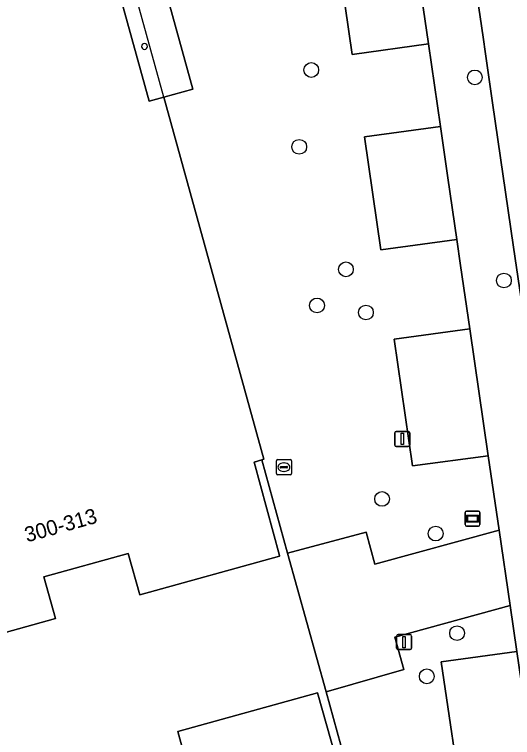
# Model space of a CAD drawing. Extents: x 159053 to 160042, y 380449 to 381423.
# Drawn here: x 159271.09 to 159304.08, y 381110.68 to 381158.52 of the extents above; entities that cross this region are included whole.
import ezdxf

# ---------------------------------------------------------------- set-up
doc = ezdxf.new("R2010")
doc.units = 0
for name, color, linetype in [('IMGEO_Boom', 7, 'Continuous'), ('IMGEO_Erf', 7, 'Continuous'), ('IMGEO_Groenvoorziening', 7, 'Continuous'), ('IMGEO_Informatiebord', 7, 'Continuous'), ('IMGEO_Lichtmast', 7, 'Continuous'), ('IMGEO_Pand', 7, 'Continuous'), ('IMGEO_Pand_nummerreeks', 7, 'Continuous'), ('IMGEO_Pand_overbouw', 7, 'Continuous'), ('IMGEO_Parkeervlak_open', 7, 'Continuous'), ('IMGEO_Rijbaan_lokaal_open', 7, 'Continuous'), ('IMGEO_Rioolput', 7, 'Continuous'), ('IMGEO_Verkeersbordpaal', 7, 'Continuous'), ('IMGEO_Voetpad_open', 7, 'Continuous')]:
    doc.layers.add(name, color=color, linetype=linetype)

msp = doc.modelspace()

# ---------------------------------------------------------------- linework, layer by layer
at = {"layer": 'IMGEO_Boom'}
for centre in [(159290.748, 381154.842), (159301.582, 381154.349), (159289.951, 381149.757), (159293.046, 381141.653), (159303.506, 381140.914), (159291.131, 381139.263), (159294.371, 381138.796), (159295.438, 381126.463), (159298.991, 381124.172), (159300.405, 381117.58), (159298.401, 381114.722)]:
    msp.add_circle(centre, 0.489, dxfattribs=at)
at = {"layer": 'IMGEO_Erf'}
msp.add_lwpolyline([(159267.012, 381106.896), (159276.276, 381109.489), (159277.044, 381106.744), (159282.667, 381108.318), (159281.903, 381111.077), (159291.153, 381113.639), (159292.923, 381107.382), (159293.441, 381107.525), (159291.727, 381113.703), (159289.185, 381122.866), (159287.469, 381129.052), (159286.976, 381128.898), (159288.643, 381122.722), (159288.656, 381122.674), (159279.389, 381120.108), (159278.627, 381122.858), (159273.045, 381121.304), (159273.81, 381118.558), (159264.542, 381115.978)], dxfattribs=at)
at = {"layer": 'IMGEO_Groenvoorziening'}
for points in [[(159269.491, 381169.977), (159277.74, 381172.284), (159278.791, 381168.465), (159282.912, 381153.581), (159280.978, 381153.047), (159287.62, 381129.099), (159287.469, 381129.052), (159289.185, 381122.866), (159294.391, 381124.259), (159294.952, 381122.145), (159303.192, 381124.392), (159302.473, 381129.318), (159297.464, 381128.646), (159296.246, 381137.035), (159301.249, 381137.708), (159300.637, 381141.908), (159300.386, 381143.634), (159295.361, 381142.946), (159294.267, 381150.411), (159299.3, 381151.1), (159298.503, 381156.571), (159293.468, 381155.863), (159292.017, 381165.794)], [(159301.734, 381099.495), (159306.727, 381100.183), (159305.82, 381106.393), (159300.832, 381105.715), (159299.362, 381115.674), (159304.363, 381116.374), (159303.921, 381119.402), (159296.289, 381117.311), (159296.87, 381115.183), (159291.727, 381113.703), (159293.441, 381107.525), (159293.597, 381107.568), (159302.903, 381073.889), (159297.014, 381072.255), (159297.723, 381069.615), (159285.651, 381066.276), (159287.134, 381060.86), (159289.094, 381061.4), (159287.696, 381066.465), (159297.411, 381069.143), (159298.793, 381064.19), (159309.233, 381066.896)]]:
    msp.add_lwpolyline(points, dxfattribs=at)
at = {"layer": 'IMGEO_Informatiebord'}
for p, q in [((159300.931, 381124.763), (159300.931, 381125.563)), ((159300.931, 381125.563), (159300.931, 381124.763)), ((159301.031, 381125.663), (159301.821, 381125.663)), ((159301.821, 381125.663), (159301.031, 381125.663)), ((159301.921, 381125.563), (159301.921, 381124.763)), ((159301.921, 381124.763), (159301.921, 381125.563)), ((159301.821, 381124.663), (159301.031, 381124.663)), ((159301.031, 381124.663), (159301.821, 381124.663))]:
    msp.add_line(p, q, dxfattribs=at)
for points in [[(159301.032, 381125.395), (159301.82, 381125.395), (159301.82, 381124.931), (159301.032, 381124.931), (159301.032, 381125.395)], [(159301.097, 381125.33), (159301.097, 381124.996), (159301.755, 381124.996), (159301.755, 381125.33), (159301.097, 381125.33)]]:
    msp.add_lwpolyline(points, dxfattribs=at)
for centre, start, end in [((159301.031, 381125.563), 90, 180), ((159301.031, 381125.563), 90, 180), ((159301.821, 381125.563), 0, 90), ((159301.821, 381125.563), 360, 90), ((159301.031, 381124.763), 180, 270), ((159301.031, 381124.763), 180, 270), ((159301.821, 381124.763), 270, 0), ((159301.821, 381124.763), 270, 0)]:
    msp.add_arc(centre, 0.1, start, end, dxfattribs=at)
at = {"layer": 'IMGEO_Lichtmast'}
for p, q in [((159296.403, 381116.593), (159296.403, 381117.393)), ((159296.403, 381117.393), (159296.403, 381116.593)), ((159296.503, 381117.493), (159297.293, 381117.493)), ((159297.293, 381117.493), (159296.503, 381117.493)), ((159297.393, 381117.393), (159297.393, 381116.593)), ((159297.393, 381116.593), (159297.393, 381117.393)), ((159297.293, 381116.493), (159296.503, 381116.493)), ((159296.503, 381116.493), (159297.293, 381116.493))]:
    msp.add_line(p, q, dxfattribs=at)
msp.add_lwpolyline([(159296.823, 381117.368), (159296.973, 381117.368), (159296.973, 381116.618), (159296.823, 381116.618), (159296.823, 381117.368)], dxfattribs=at)
for centre, start, end in [((159296.503, 381117.393), 90, 180), ((159296.503, 381117.393), 90, 180), ((159297.293, 381117.393), 0, 90), ((159297.293, 381117.393), 360, 90), ((159296.503, 381116.593), 180, 270), ((159296.503, 381116.593), 180, 270), ((159297.293, 381116.593), 270, 0), ((159297.293, 381116.593), 270, 0)]:
    msp.add_arc(centre, 0.1, start, end, dxfattribs=at)
at = {"layer": 'IMGEO_Pand'}
msp.add_lwpolyline([(159253.135, 381159.05), (159253.4, 381158.117), (159253.22, 381158.059), (159254.513, 381153.32), (159253.576, 381153.044), (159257.602, 381138.448), (159259.222, 381132.575), (159262.133, 381122.02), (159262.266, 381122.057), (159262.808, 381122.207), (159264.542, 381115.978), (159273.81, 381118.558), (159273.045, 381121.304), (159278.627, 381122.858), (159279.389, 381120.108), (159288.656, 381122.674), (159288.643, 381122.722), (159286.976, 381128.898), (159287.469, 381129.052), (159287.62, 381129.099), (159280.978, 381153.047), (159280.014, 381152.78), (159276.743, 381164.603)], dxfattribs=at)
msp.add_lwpolyline([(159293.441, 381107.525), (159292.923, 381107.382), (159291.153, 381113.639), (159281.903, 381111.077), (159282.667, 381108.318), (159277.044, 381106.744), (159276.276, 381109.489), (159267.012, 381106.896), (159268.748, 381100.692), (159268.237, 381100.56), (159268.076, 381100.519), (159277.368, 381066.826), (159283.772, 381068.592), (159283.457, 381069.734), (159296.316, 381073.297), (159296.633, 381072.15), (159297.014, 381072.255), (159302.903, 381073.889), (159293.597, 381107.568)], close=True, dxfattribs=at)
for start, end in [(90, 270), (270, 90)]:
    msp.add_arc((159279.706, 381156.398), 0.2, start, end, dxfattribs=at)
at = {"layer": 'IMGEO_Pand_overbouw'}
msp.add_lwpolyline([(159276.743, 381164.603), (159280.014, 381152.78), (159280.978, 381153.047), (159277.135, 381166.934)], dxfattribs=at)
at = {"layer": 'IMGEO_Parkeervlak_open'}
for points in [[(159297.057, 381166.506), (159292.017, 381165.794), (159293.468, 381155.863), (159298.503, 381156.571)], [(159299.3, 381151.1), (159294.267, 381150.411), (159295.361, 381142.946), (159300.386, 381143.634), (159299.795, 381147.696)], [(159301.249, 381137.708), (159296.246, 381137.035), (159297.464, 381128.646), (159302.473, 381129.318)], [(159299.362, 381115.674), (159300.832, 381105.715), (159305.82, 381106.393), (159304.363, 381116.374)]]:
    msp.add_lwpolyline(points, close=True, dxfattribs=at)
at = {"layer": 'IMGEO_Rijbaan_lokaal_open'}
msp.add_lwpolyline([(159298.315, 381182.944), (159298.504, 381181.554), (159299.889, 381172.19), (159300.509, 381167.999), (159301.731, 381159.728), (159302.132, 381157.016), (159302.294, 381155.916), (159302.763, 381152.666), (159304.139, 381143.129), (159304.737, 381139.073), (159311.448, 381140.008), (159308.825, 381157.991), (159308.429, 381160.702), (159305.646, 381179.78)], dxfattribs=at)
at = {"layer": 'IMGEO_Rioolput'}
for p, q in [((159288.437, 381128.136), (159288.437, 381128.988)), ((159288.512, 381129.062), (159289.364, 381129.062)), ((159288.925, 381128.842), (159288.95, 381128.842)), ((159289.438, 381128.988), (159289.438, 381128.136)), ((159288.696, 381128.556), (159288.696, 381128.568)), ((159289.134, 381128.519), (159288.736, 381128.519)), ((159288.739, 381128.605), (159289.137, 381128.605)), ((159288.948, 381128.282), (159288.923, 381128.282)), ((159289.18, 381128.568), (159289.18, 381128.556)), ((159289.364, 381128.062), (159288.512, 381128.062))]:
    msp.add_line(p, q, dxfattribs=at)
for points in [[(159288.437, 381128.136), (159288.437, 381128.988)], [(159288.512, 381129.062), (159289.364, 381129.062)], [(159289.438, 381128.988), (159289.438, 381128.136)], [(159289.364, 381128.062), (159288.512, 381128.062)]]:
    msp.add_lwpolyline(points, dxfattribs=at)
for centre, radius, start, end in [((159288.514, 381128.986), 0.0765, 91.552, 178.448), ((159288.514, 381128.986), 0.0765, 91.552, 178.448), ((159289.362, 381128.986), 0.0765, 1.552, 88.448), ((159289.362, 381128.986), 0.0765, 1.552, 88.448), ((159288.736, 381128.565), 0.0403, 85.8775, 175.7526), ((159288.733, 381128.555), 0.0366, 178.938, 274.7102), ((159289.137, 381128.562), 0.043, 264.8664, 352.4533), ((159289.141, 381128.567), 0.0386, 1.7309, 96.639), ((159288.514, 381128.138), 0.0765, 181.552, 268.448), ((159288.514, 381128.138), 0.0765, 181.552, 268.448), ((159289.362, 381128.138), 0.0765, 271.552, 358.448), ((159289.362, 381128.138), 0.0765, 271.552, 358.448)]:
    msp.add_arc(centre, radius, start, end, dxfattribs=at)
for centre, major_axis, ratio, start_param, end_param in [((159288.924, 381128.562), (-0.387, 0.002), 0.722429, 4.712389, 7.853982), ((159288.949, 381128.562), (-0.39, 0.002), 0.717154, 1.570796, 4.712389)]:
    msp.add_ellipse(centre, major_axis=major_axis, ratio=ratio, start_param=start_param, end_param=end_param, dxfattribs=at)
at = {"layer": 'IMGEO_Verkeersbordpaal'}
for p, q in [((159296.278, 381130.03), (159296.278, 381130.83)), ((159296.278, 381130.83), (159296.278, 381130.03)), ((159296.378, 381130.93), (159297.168, 381130.93)), ((159297.168, 381130.93), (159296.378, 381130.93)), ((159297.268, 381130.83), (159297.268, 381130.03)), ((159297.268, 381130.03), (159297.268, 381130.83)), ((159297.168, 381129.93), (159296.378, 381129.93)), ((159296.378, 381129.93), (159297.168, 381129.93))]:
    msp.add_line(p, q, dxfattribs=at)
msp.add_lwpolyline([(159296.698, 381130.805), (159296.848, 381130.805), (159296.848, 381130.055), (159296.698, 381130.055), (159296.698, 381130.805)], dxfattribs=at)
for centre, start, end in [((159296.378, 381130.83), 90, 180), ((159296.378, 381130.83), 90, 180), ((159297.168, 381130.83), 0, 90), ((159297.168, 381130.83), 360, 90), ((159296.378, 381130.03), 180, 270), ((159296.378, 381130.03), 180, 270), ((159297.168, 381130.03), 270, 0), ((159297.168, 381130.03), 270, 0)]:
    msp.add_arc(centre, 0.1, start, end, dxfattribs=at)
at = {"layer": 'IMGEO_Voetpad_open'}
for points in [[(159306.19, 381129.099), (159304.757, 381138.939), (159304.737, 381139.073), (159304.139, 381143.129), (159302.763, 381152.666), (159302.294, 381155.916), (159302.132, 381157.016), (159301.731, 381159.728), (159300.509, 381167.999), (159299.889, 381172.19), (159298.504, 381181.554), (159298.315, 381182.944)], [(159294.912, 381182.231), (159295.246, 381179.972), (159295.395, 381178.961), (159295.968, 381174.666), (159296.278, 381172.341), (159297.057, 381166.506), (159298.503, 381156.571), (159299.3, 381151.1), (159299.795, 381147.696), (159300.386, 381143.634), (159300.637, 381141.908), (159301.249, 381137.708), (159302.473, 381129.318), (159303.192, 381124.392), (159303.921, 381119.402), (159304.363, 381116.374), (159305.82, 381106.393), (159306.727, 381100.183), (159308.151, 381090.241), (159309.044, 381084.316), (159310.329, 381076.855), (159311.284, 381070.128)], [(159276.743, 381164.603), (159280.014, 381152.78), (159280.978, 381153.047), (159282.912, 381153.581), (159278.791, 381168.465)]]:
    msp.add_lwpolyline(points, dxfattribs=at)
msp.add_lwpolyline([(159303.192, 381124.392), (159294.952, 381122.145), (159294.391, 381124.259), (159289.185, 381122.866), (159291.727, 381113.703), (159296.87, 381115.183), (159296.289, 381117.311), (159303.921, 381119.402)], close=True, dxfattribs=at)
for start, end in [(90, 270), (270, 90)]:
    msp.add_arc((159279.706, 381156.398), 0.2, start, end, dxfattribs=at)

# ---------------------------------------------------------------- texts
at = {"layer": 'IMGEO_Pand_nummerreeks'}
msp.add_text('300-313', height=1, rotation=15.5672, dxfattribs=at).set_placement((159271.923, 381123.585))

doc.saveas('drawing.dxf')
